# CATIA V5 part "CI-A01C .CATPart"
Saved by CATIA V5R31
Part number: IN-OUT CHAIR- COMPLETA
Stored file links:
  C:\Users\simone\Dropbox\3DTECH\Cassina - Catalogo Custom Interiors\MODELLI 3D\DEFINITIVI\ESPORTATI\IN-OUT CHAIR- SIN CHAIR\IN-OUT CHAIR- COMPLETA.CATPart

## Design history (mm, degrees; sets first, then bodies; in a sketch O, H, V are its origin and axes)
Body1 "Solido1" (main body)
  Solid1: solid without history
Body2 "Solido8"
  Solid2: solid without history
Body3 "Solido9"
  Solid3: solid without history
Body4 "PIPING SCHIENALE"
  Solid4: solid without history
